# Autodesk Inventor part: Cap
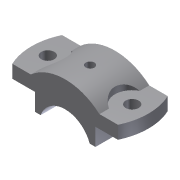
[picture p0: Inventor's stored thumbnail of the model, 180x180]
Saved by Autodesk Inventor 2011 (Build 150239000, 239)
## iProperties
Created: 2009-04
Part Number: Cap
Document SubType Name: Modeling
Designer: Sham
Density: 1 g/cm^3
Author: Sham
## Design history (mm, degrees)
sketch "Sketch1"
  geometry: L1 (-48.857, 23)-(48.857, 23); L2 (48.857, -23)-(-48.857, -23); A1 r 54 centre (0, 0) between (-48.857, 23) and (-48.857, -23); A2 r 54 centre (0, 0) between (48.857, -23) and (48.857, 23); 1 further point
  constraints: 4 end point, 4 point on circle, 2 centre point, 2 coincident, 1 horizontal, 1 parallel, 1 other
  dimensions: "d3" = 54 radius of A1; "d4" = 54 radius of A2; "d5" = 46 distance between parallel lines of L2 L1; "d6" = 23 distance from line of point (0, 0) L1
extrude "Extrusion1" new body sketch "Sketch1" distance "d7" = 12; taper "d8" = 0 deg
sketch "Sketch3"
  geometry: L1 (20.906, 0)-(20.906, -16); L2 (76.906, -0.137)-(76.906, -16.137); L3 (20.906, -16)-(26.23, -16); L4 (71.532, -16.137)-(76.906, -16.137); L5 (76.906, -0.137)-(76.857, 12); L6 (97.714, 0)-(0, 0) reference; L7 (76.857, 12)-(80.606, 12); L8 (17.108, 12)-(20.906, 12); L9 (20.906, 12)-(20.906, 0); L10 (0, 12)-(97.714, 12) reference; A1 r 24 centre (48.857, -24) between (71.532, -16.137) and (26.23, -16); A2 r 48 centre (48.857, -24) between (80.606, 12) and (17.108, 12); 3 further points
  constraints: 16 end point, 4 point on circle, 3 parallel, 3 perpendicular, 2 centre point, 2 coincident, 2 vertical alignment, 1 collinear, 1 midpoint, 1 vertical, 2 other
  dimensions: "d17" = 48 diameter of A1; "d18" = 16 distance of L1.start L1.end; "d19" = 56 distance between parallel lines of L2 L1; "d21" = 8 vertical distance of A1.centre L1.end; "d22" = 48 radius of A2; "d23" = 0 distance from line of L6 L1.start; "d38" = 31.74902 distance of L7.end point (48.857, 12); "d39" = 28 distance from line of point (48.857, 12) L5
extrude "Extrusion2" join sketch "Sketch3" stored distance "d24" = 12; taper "d25" = 0 deg
sketch "Sketch4"
  geometry: 2 further points
  dimensions: "d26" = 78 distance of point (39, 0) point (-39, 0)
hole "Hole1" sketch "Sketch4" at (-39, 0), (39, 0) diameter "d28" = 12; stored, may be unused: countersink angle "d32" = 90 deg, drill point angle "d34" = 118 deg; dims "d29" = 6, "d30" = 4, "d31" = 2, "d33" = 8
sketch "Sketch5"
  geometry: L1 (-31.749, -23)-(-31.749, 23) reference; L2 (-31.749, 14.263)-(-31.749, -14.263); C1 r 6 at (-39, 0) reference; A1 r 16 centre (-39, 0) between (-31.749, -14.263) and (-31.749, 14.263)
  constraints: 2 end point, 2 point on circle, 1 centre point, 1 coincident, 1 collinear, 1 point on line
  dimensions: "d35" = 16 radius of A1
extrude "Extrusion3" cut sketch "Sketch5" distance "d36" = 12; taper "d37" = 0 deg
mirror "Mirror2"
workplane "Work Plane4"
sketch "Sketch6"
  geometry: L1 (-31.749, 0)-(31.749, 0) reference; 1 further point
  dimensions: "d40" = 23 distance from line of L1 point (0, 23)
hole "Hole2" sketch "Sketch6" at (0, 23) diameter "d41" = 6; stored, may be unused: countersink angle "d45" = 90 deg, drill point angle "d47" = 118 deg; dims "d42" = 6, "d43" = 8, "d44" = 16, "d46" = 8
body "Solid1"
